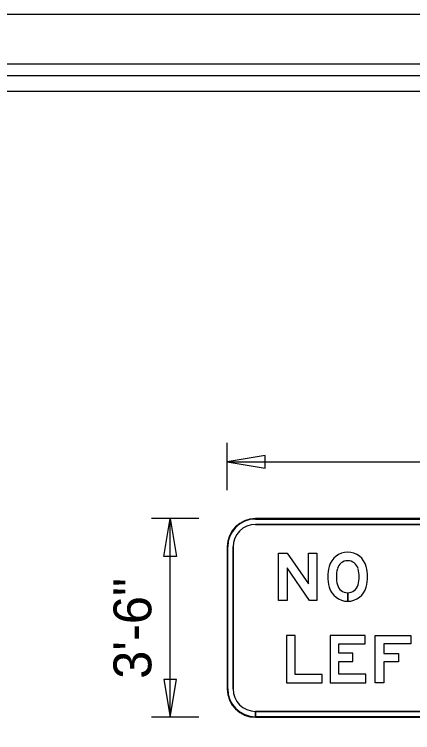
# Model space of a CAD drawing. Extents: x 17890628 to 17890844, y 17897508 to 17897992.
# Drawn here: x 17890808.72 to 17890815.73, y 17897587.47 to 17897600.12 of the extents above; entities that cross this region are included whole.
import ezdxf

# ---------------------------------------------------------------- set-up
doc = ezdxf.new("R2010")
doc.units = 0
for name, color, linetype in [('GSBWFill', 7, 'Continuous'), ('GSColorFill', 7, 'Continuous'), ('GSDims', 7, 'Continuous'), ('GSOutline', 7, 'Continuous'), ('PlotBorder_dp', 7, 'Continuous'), ('SheetBorder_dp', 7, 'Continuous'), ('SheetLinesMisc2_dp', 7, 'Continuous')]:
    doc.layers.add(name, color=color, linetype=linetype)

msp = doc.modelspace()

# ---------------------------------------------------------------- linework, layer by layer
at = {"layer": 'GSBWFill'}
for p, q in [((17890820.967, 17897591.239), (17890812.967, 17897591.239)), ((17890812.967, 17897591.134), (17890820.967, 17897591.134)), ((17890812.467, 17897590.739), (17890812.467, 17897588.239)), ((17890812.571, 17897588.239), (17890812.571, 17897590.739)), ((17890814.588, 17897589.783), (17890814.588, 17897589.933)), ((17890814.588, 17897589.933), (17890814.588, 17897589.783)), ((17890812.967, 17897587.739), (17890812.967, 17897587.843)), ((17890820.967, 17897587.843), (17890812.968, 17897587.843)), ((17890812.968, 17897587.843), (17890812.968, 17897587.739)), ((17890812.968, 17897587.739), (17890820.967, 17897587.739))]:
    msp.add_line(p, q, dxfattribs=at)
for points in [[(17890814.046, 17897590.631), (17890814.046, 17897589.797), (17890813.917, 17897589.797), (17890813.521, 17897590.368), (17890813.521, 17897589.797), (17890813.371, 17897589.797), (17890813.371, 17897590.631), (17890813.522, 17897590.631), (17890813.896, 17897590.091), (17890813.896, 17897590.631)], [(17890814.138, 17897588.346), (17890814.138, 17897588.492), (17890813.663, 17897588.492), (17890813.663, 17897589.18), (17890813.513, 17897589.18), (17890813.513, 17897588.346)], [(17890814.905, 17897588.496), (17890814.43, 17897588.496), (17890814.43, 17897588.721), (17890814.675, 17897588.721), (17890814.675, 17897588.871), (17890814.43, 17897588.871), (17890814.43, 17897589.03), (17890814.892, 17897589.03), (17890814.892, 17897589.18), (17890814.28, 17897589.18), (17890814.28, 17897588.346), (17890814.905, 17897588.346)], [(17890815.221, 17897588.713), (17890815.221, 17897588.346), (17890815.071, 17897588.346), (17890815.071, 17897589.18), (17890815.696, 17897589.18), (17890815.696, 17897589.03), (17890815.221, 17897589.03), (17890815.221, 17897588.863), (17890815.484, 17897588.863), (17890815.484, 17897588.713)]]:
    msp.add_lwpolyline(points, close=True, dxfattribs=at)
for centre, radius, start, end in [((17890812.967, 17897590.739), 0.5, 90, 180), ((17890812.967, 17897590.739), 0.396, 90, 180), ((17890812.967, 17897588.239), 0.5, 180, 270), ((17890812.967, 17897588.239), 0.396, 180, 270)]:
    msp.add_arc(centre, radius, start, end, dxfattribs=at)
for centre, major_axis, start_param, end_param in [((17890814.588, 17897590.308), (0, 0.338), 4.973521, 7.592849), ((17890814.588, 17897590.308), (0, 0.188), 4.973521, 7.592849), ((17890814.938, 17897590.214), (0, 0.7), 1.309664, 1.831929), ((17890814.238, 17897590.214), (0, 0.7), 4.451257, 4.973521), ((17890814.938, 17897590.214), (0, 0.55), 1.309664, 1.831929), ((17890814.238, 17897590.214), (0, 0.55), 4.451257, 4.973521), ((17890814.588, 17897590.12), (0, 0.338), 1.831929, 3.141593), ((17890814.588, 17897590.12), (0, 0.188), 1.831929, 3.141593), ((17890814.588, 17897590.12), (0, 0.188), 3.141815, 4.451257), ((17890814.588, 17897590.12), (0, 0.338), 3.141716, 4.451257)]:
    msp.add_ellipse(centre, major_axis=major_axis, ratio=0.999997, start_param=start_param, end_param=end_param, dxfattribs=at)
at = {"layer": 'GSColorFill'}
for p, q in [((17890820.967, 17897591.239), (17890812.967, 17897591.239)), ((17890820.967, 17897591.239), (17890812.967, 17897591.239)), ((17890820.967, 17897591.239), (17890812.967, 17897591.239)), ((17890812.967, 17897591.228), (17890820.967, 17897591.228)), ((17890812.967, 17897591.134), (17890820.967, 17897591.134)), ((17890812.467, 17897590.739), (17890812.467, 17897588.239)), ((17890812.467, 17897590.739), (17890812.467, 17897588.239)), ((17890812.467, 17897590.739), (17890812.467, 17897588.239)), ((17890812.477, 17897588.239), (17890812.477, 17897590.739)), ((17890812.571, 17897588.239), (17890812.571, 17897590.739)), ((17890814.588, 17897589.783), (17890814.588, 17897589.933)), ((17890814.588, 17897589.933), (17890814.588, 17897589.783)), ((17890812.967, 17897587.739), (17890812.967, 17897587.843)), ((17890820.967, 17897587.843), (17890812.968, 17897587.843)), ((17890812.968, 17897587.843), (17890812.968, 17897587.739)), ((17890812.967, 17897587.739), (17890812.967, 17897587.749)), ((17890820.967, 17897587.749), (17890812.967, 17897587.749)), ((17890812.967, 17897587.749), (17890812.967, 17897587.739)), ((17890812.967, 17897587.739), (17890820.967, 17897587.739)), ((17890812.967, 17897587.739), (17890820.967, 17897587.739)), ((17890812.968, 17897587.739), (17890820.967, 17897587.739))]:
    msp.add_line(p, q, dxfattribs=at)
for points in [[(17890814.046, 17897590.631), (17890814.046, 17897589.797), (17890813.917, 17897589.797), (17890813.521, 17897590.368), (17890813.521, 17897589.797), (17890813.371, 17897589.797), (17890813.371, 17897590.631), (17890813.522, 17897590.631), (17890813.896, 17897590.091), (17890813.896, 17897590.631)], [(17890814.138, 17897588.346), (17890814.138, 17897588.492), (17890813.663, 17897588.492), (17890813.663, 17897589.18), (17890813.513, 17897589.18), (17890813.513, 17897588.346)], [(17890814.905, 17897588.496), (17890814.43, 17897588.496), (17890814.43, 17897588.721), (17890814.675, 17897588.721), (17890814.675, 17897588.871), (17890814.43, 17897588.871), (17890814.43, 17897589.03), (17890814.892, 17897589.03), (17890814.892, 17897589.18), (17890814.28, 17897589.18), (17890814.28, 17897588.346), (17890814.905, 17897588.346)], [(17890815.221, 17897588.713), (17890815.221, 17897588.346), (17890815.071, 17897588.346), (17890815.071, 17897589.18), (17890815.696, 17897589.18), (17890815.696, 17897589.03), (17890815.221, 17897589.03), (17890815.221, 17897588.863), (17890815.484, 17897588.863), (17890815.484, 17897588.713)]]:
    msp.add_lwpolyline(points, close=True, dxfattribs=at)
for centre, radius, start, end in [((17890812.967, 17897590.739), 0.5, 90, 180), ((17890812.967, 17897590.739), 0.5, 90, 180), ((17890812.967, 17897590.739), 0.5, 90, 180), ((17890812.967, 17897590.739), 0.49, 90, 180), ((17890812.967, 17897590.739), 0.396, 90, 180), ((17890812.967, 17897588.239), 0.5, 180, 270), ((17890812.967, 17897588.239), 0.5, 180, 270), ((17890812.967, 17897588.239), 0.5, 180, 270), ((17890812.967, 17897588.239), 0.49, 180, 270), ((17890812.967, 17897588.239), 0.396, 180, 270)]:
    msp.add_arc(centre, radius, start, end, dxfattribs=at)
for centre, major_axis, start_param, end_param in [((17890814.588, 17897590.308), (0, 0.338), 4.973521, 7.592849), ((17890814.588, 17897590.308), (0, 0.188), 4.973521, 7.592849), ((17890814.938, 17897590.214), (0, 0.7), 1.309664, 1.831929), ((17890814.238, 17897590.214), (0, 0.7), 4.451257, 4.973521), ((17890814.938, 17897590.214), (0, 0.55), 1.309664, 1.831929), ((17890814.238, 17897590.214), (0, 0.55), 4.451257, 4.973521), ((17890814.588, 17897590.12), (0, 0.338), 1.831929, 3.141593), ((17890814.588, 17897590.12), (0, 0.188), 1.831929, 3.141593), ((17890814.588, 17897590.12), (0, 0.188), 3.141815, 4.451257), ((17890814.588, 17897590.12), (0, 0.338), 3.141716, 4.451257)]:
    msp.add_ellipse(centre, major_axis=major_axis, ratio=0.999997, start_param=start_param, end_param=end_param, dxfattribs=at)
at = {"layer": 'GSDims'}
for p, q in [((17890812.467, 17897591.739), (17890812.467, 17897592.572)), ((17890812.467, 17897592.239), (17890821.467, 17897592.239)), ((17890811.967, 17897591.239), (17890811.134, 17897591.239)), ((17890811.467, 17897587.739), (17890811.467, 17897591.239)), ((17890811.967, 17897587.739), (17890811.134, 17897587.739))]:
    msp.add_line(p, q, dxfattribs=at)
for points in [[(17890812.467, 17897592.239), (17890813.134, 17897592.127), (17890813.134, 17897592.35)], [(17890811.467, 17897591.239), (17890811.578, 17897590.572), (17890811.356, 17897590.572)], [(17890811.467, 17897587.739), (17890811.578, 17897588.405), (17890811.356, 17897588.405)]]:
    msp.add_lwpolyline(points, close=True, dxfattribs=at)
at = {"layer": 'GSOutline'}
for p, q in [((17890820.967, 17897591.239), (17890812.967, 17897591.239)), ((17890820.967, 17897591.134), (17890812.967, 17897591.134)), ((17890812.467, 17897590.739), (17890812.467, 17897588.239)), ((17890812.571, 17897590.739), (17890812.571, 17897588.239)), ((17890812.967, 17897587.843), (17890820.967, 17897587.843)), ((17890812.967, 17897587.739), (17890820.967, 17897587.739))]:
    msp.add_line(p, q, dxfattribs=at)
for points in [[(17890814.046, 17897590.631), (17890814.046, 17897589.797), (17890813.917, 17897589.797), (17890813.521, 17897590.368), (17890813.521, 17897589.797), (17890813.371, 17897589.797), (17890813.371, 17897590.631), (17890813.522, 17897590.631), (17890813.896, 17897590.091), (17890813.896, 17897590.631)], [(17890814.138, 17897588.346), (17890814.138, 17897588.492), (17890813.663, 17897588.492), (17890813.663, 17897589.18), (17890813.513, 17897589.18), (17890813.513, 17897588.346)], [(17890814.905, 17897588.496), (17890814.43, 17897588.496), (17890814.43, 17897588.721), (17890814.675, 17897588.721), (17890814.675, 17897588.871), (17890814.43, 17897588.871), (17890814.43, 17897589.03), (17890814.892, 17897589.03), (17890814.892, 17897589.18), (17890814.28, 17897589.18), (17890814.28, 17897588.346), (17890814.905, 17897588.346)], [(17890815.221, 17897588.713), (17890815.221, 17897588.346), (17890815.071, 17897588.346), (17890815.071, 17897589.18), (17890815.696, 17897589.18), (17890815.696, 17897589.03), (17890815.221, 17897589.03), (17890815.221, 17897588.863), (17890815.484, 17897588.863), (17890815.484, 17897588.713)]]:
    msp.add_lwpolyline(points, close=True, dxfattribs=at)
for centre, radius, start, end in [((17890812.967, 17897590.739), 0.5, 90, 180), ((17890812.967, 17897590.739), 0.396, 90, 180), ((17890812.967, 17897588.239), 0.5, 180, 270), ((17890812.967, 17897588.239), 0.396, 180, 270)]:
    msp.add_arc(centre, radius, start, end, dxfattribs=at)
for centre, major_axis, start_param, end_param in [((17890814.588, 17897590.308), (0, 0.338), 4.973521, 7.592849), ((17890814.588, 17897590.308), (0, 0.188), 4.973521, 7.592849), ((17890814.938, 17897590.214), (0, 0.7), 1.309664, 1.831929), ((17890814.238, 17897590.214), (0, 0.7), 4.451257, 4.973521), ((17890814.938, 17897590.214), (0, 0.55), 1.309664, 1.831929), ((17890814.238, 17897590.214), (0, 0.55), 4.451257, 4.973521), ((17890814.588, 17897590.12), (0, 0.338), 1.831929, 4.451257), ((17890814.588, 17897590.12), (0, 0.188), 1.831929, 4.451257)]:
    msp.add_ellipse(centre, major_axis=major_axis, ratio=0.999997, start_param=start_param, end_param=end_param, dxfattribs=at)
at = {"layer": 'PlotBorder_dp'}
msp.add_lwpolyline([(17890700.471, 17897507.741), (17890844.259, 17897507.741), (17890844.259, 17897600.116), (17890700.471, 17897600.116)], close=True, dxfattribs=at)
at = {"layer": 'SheetBorder_dp'}
msp.add_line((17890705.263, 17897599.245), (17890839.466, 17897599.245), dxfattribs=at)
at = {"layer": 'SheetLinesMisc2_dp'}
for p, q in [((17890705.5, 17897599.039), (17890839.233, 17897599.039)), ((17890793.11, 17897598.762), (17890838.594, 17897598.762))]:
    msp.add_line(p, q, dxfattribs=at)

# ---------------------------------------------------------------- texts
at = {"layer": 'GSDims'}
msp.add_text('3\'-6"', height=0.6667, rotation=90, dxfattribs=at).set_placement((17890811.134, 17897588.416))

doc.saveas('drawing.dxf')
